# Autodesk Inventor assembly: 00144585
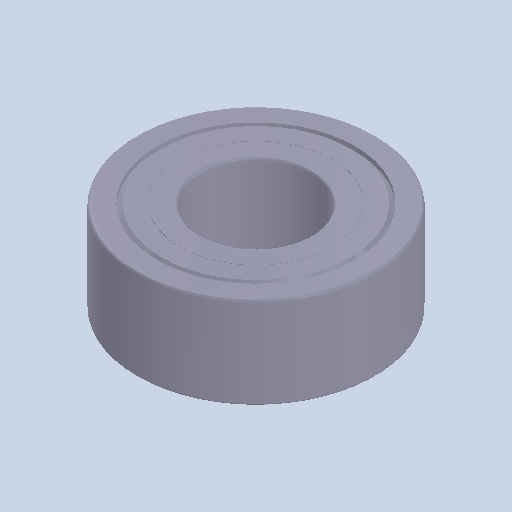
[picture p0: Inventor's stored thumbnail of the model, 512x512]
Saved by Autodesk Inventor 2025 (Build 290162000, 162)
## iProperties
Created: 2021-02
Part Number: 00144585
Document SubType Name: Assembly
Designer: Ryzen5700u
Author: Ryzen5700u
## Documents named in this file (15)
- C:\Users\Ryzen5700u\Desktop\scara\Assieme_scara_03\00144585.iam
- C:\Users\Ryzen5700u\Desktop\scara\Assieme_scara_03\00144585_01.ipt
- C:\Users\Ryzen5700u\Desktop\scara\Assieme_scara_03\00144585_02.ipt
- C:\Users\Ryzen5700u\Desktop\scara\Assieme_scara_03\00144585_03.ipt
- C:\Users\Ryzen5700u\Desktop\scara\Assieme_scara_03\00144585_04.ipt
- C:\Users\Ryzen5700u\Desktop\scara\Assieme_scara_03\00144585_05.ipt
- C:\Users\Ryzen5700u\Desktop\scara\Assieme_scara_03\00144585_06.ipt
- C:\Users\Ryzen5700u\Desktop\scara\Assieme_scara_03\00144585_07.ipt
- C:\Users\Ryzen5700u\Desktop\scara\Assieme_scara_03\00144585_08.ipt
- C:\Users\Ryzen5700u\Desktop\scara\Assieme_scara_03\00144585_09.ipt
- C:\Users\Ryzen5700u\Desktop\scara\Assieme_scara_03\00144585_10.ipt
- C:\Users\Ryzen5700u\Desktop\scara\Assieme_scara_03\00144585_11.ipt
- C:\Users\Ryzen5700u\Desktop\scara\Assieme_scara_03\00144585_12.ipt
- C:\Users\Ryzen5700u\Desktop\scara\Assieme_scara_03\00144585_13.ipt
- C:\Users\Ryzen5700u\Desktop\scara\Assieme_scara_03\00144585_14.ipt
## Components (14 placed, 14 different names)
1. 00144585_01:1
2. 00144585_02:1
3. 00144585_03:1
4. 00144585_04:1
5. 00144585_05:1
6. 00144585_06:1
7. 00144585_07:1
8. 00144585_08:1
9. 00144585_09:1
10. 00144585_10:1
11. 00144585_11:1
12. 00144585_12:1
13. 00144585_13:1
14. 00144585_14:1
